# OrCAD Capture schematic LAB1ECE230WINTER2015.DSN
size A
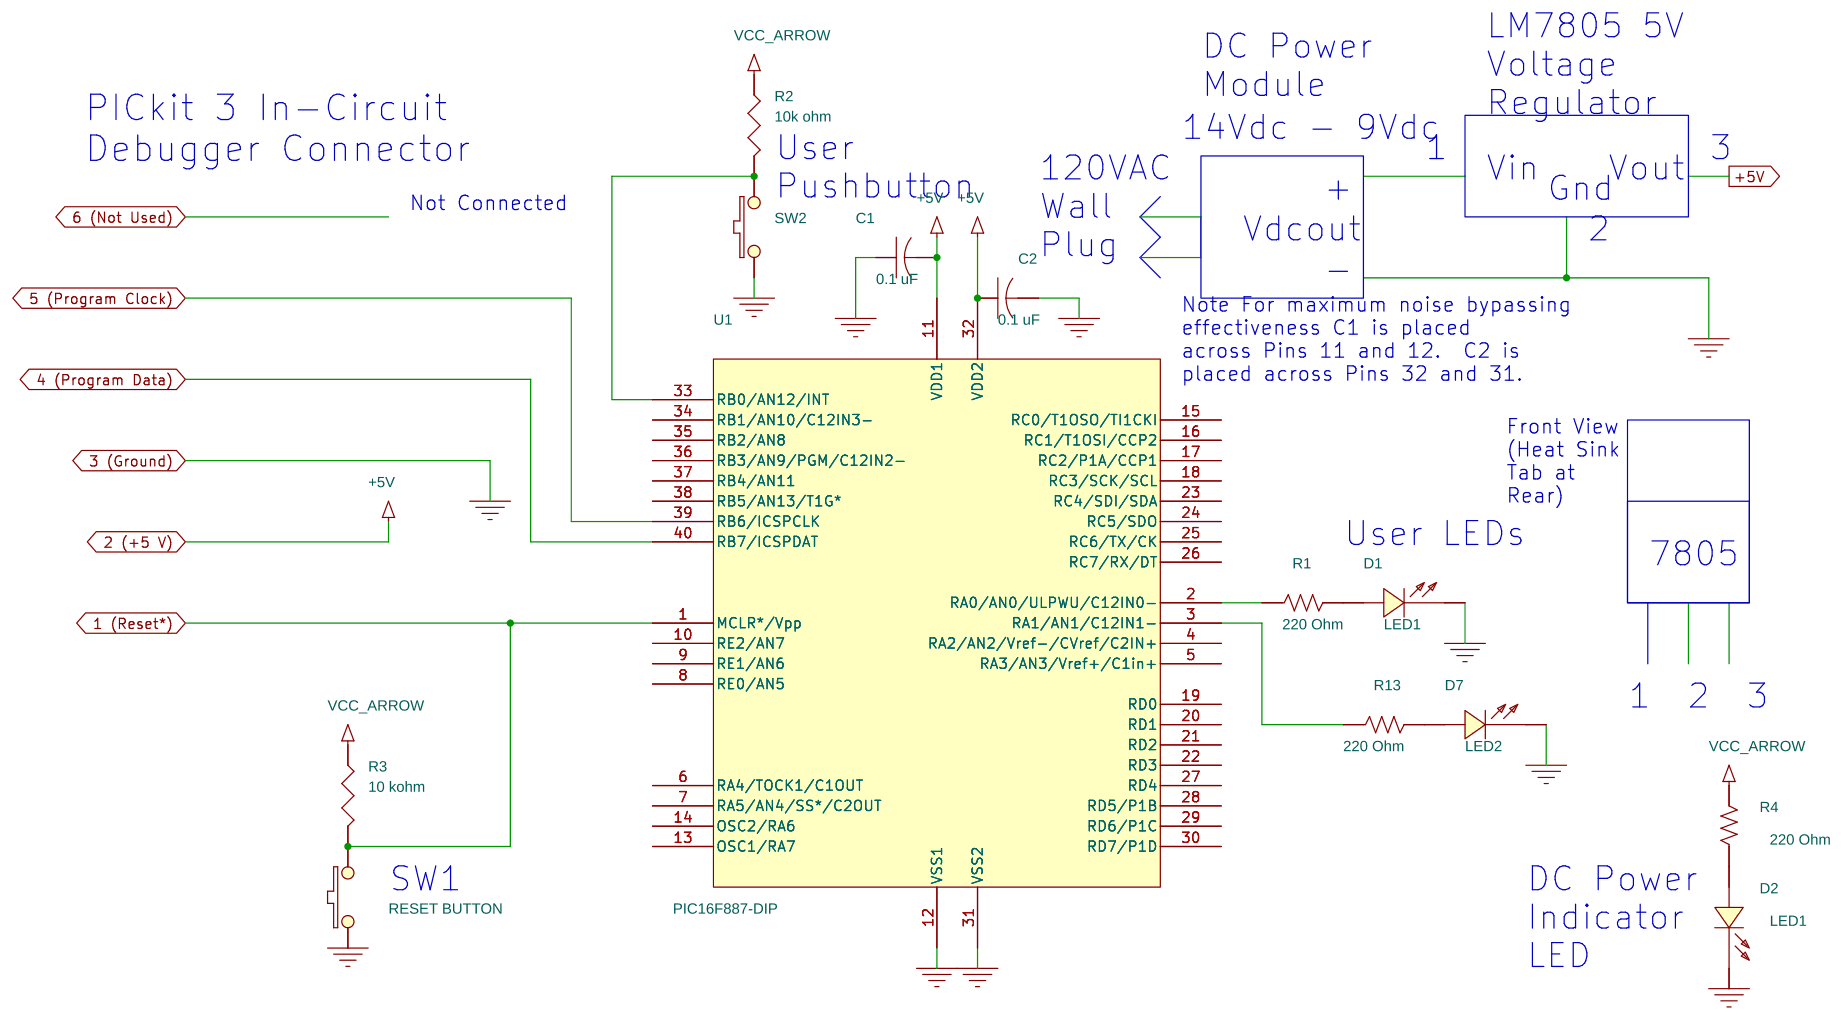
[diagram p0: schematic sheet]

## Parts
C1  0.1 uF
C2  0.1 uF
D1  LED1
D2  LED1
D7  LED2
R1  220 Ohm  [AX/RC05]
R2  10k ohm  [AX/RC05]
R3  10 kohm  [AX/RC05]
R4  220 Ohm  [AX/RC05]
R13  220 Ohm  [AX/RC05]
RESET BUTTON  SW PUSHBUTTON
SW2  SW PUSHBUTTON
U1  PIC16F887-DIP

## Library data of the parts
C1 C2 = C
D1 D2 D7 = LED
R1 R4 R13 = R_v2
R2 R3 = R
RESET BUTTON SW2 = SW_PUSHBUTTON
U1 = PIC16F887_0

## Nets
+5V: C1.2 C2.1 R2.1 R3.1 R4.2 U1.11(VDD1) U1.32(VDD2)
GND: C1.1 C2.2 D1.2(CATHODE) D2.2(CATHODE) D7.2(CATHODE) RESET BUTTON.1 SW2.1 U1.12(VSS1) U1.31(VSS2)
1 (Reset*): R3.2 RESET BUTTON.2 U1.1(MCLR*/Vpp)
4 (Program Data): U1.40(RB7/ICSPDAT)
5 (Program Clock): U1.39(RB6/ICSPCLK)
N16307: R2.2 SW2.2 U1.33(RB0/AN12/INT)
N21655: R13.1 U1.3(RA1/AN1/C12IN1-)
N21728: R1.1 U1.2(RA0/AN0/ULPWU/C12IN0-)
N21760: D2.1(ANODE) R4.1
N21770: D1.1(ANODE) R1.2
N21800: D7.1(ANODE) R13.2

Not connected (* = marked no-connect by the designer): U1 4(RA2/AN2/Vref-/CVref/C2IN+) 5(RA3/AN3/Vref+/C1in+) 6(RA4/TOCK1/C1OUT) 7(RA5/AN4/SS*/C2OUT) 8(RE0/AN5) 9(RE1/AN6) 10(RE2/AN7) 13(OSC1/RA7) 14(OSC2/RA6) 15(RC0/T1OSO/TI1CKI) 16(RC1/T1OSI/CCP2) 17(RC2/P1A/CCP1) 18(RC3/SCK/SCL) 19(RD0) 20(RD1) 21(RD2) 22(RD3) 23(RC4/SDI/SDA) 24(RC5/SDO) 25(RC6/TX/CK) 26(RC7/RX/DT) 27(RD4) 28(RD5/P1B) 29(RD6/P1C) 30(RD7/P1D) 34(RB1/AN10/C12IN3-) 35(RB2/AN8) 36(RB3/AN9/PGM/C12IN2-) 37(RB4/AN11) 38(RB5/AN13/T1G*)

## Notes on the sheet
- LM7805 5V
  Voltage
  Regulator
- DC Power
  Module
- PICkit 3 In-Circuit
  Debugger Connector
- 14Vdc - 9Vdc
- User
  Pushbutton
- 1
- 3
- 120VAC
  Wall
  Plug
- Vin
- Vout
- +
- Gnd
- Not Connected
- Vdcout
- 2
- -
- Note For maximum noise bypassing
  effectiveness C1 is placed
  across Pins 11 and 12.  C2 is
  placed across Pins 32 and 31.
- Front View
  (Heat Sink
  Tab at
  Rear)
- User LEDs
- 7805
- 1  2  3
- SW1
- DC Power
  Indicator
  LED
